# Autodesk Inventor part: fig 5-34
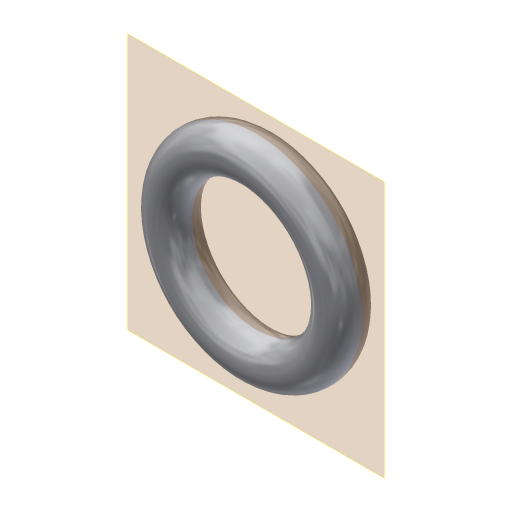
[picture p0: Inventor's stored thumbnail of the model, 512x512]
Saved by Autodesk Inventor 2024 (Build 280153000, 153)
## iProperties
Created: 2010-02
Part Number: fig 5-34
Document SubType Name: Modeling
Designer: CADSoft
Density: 1 g/cm^3
Material: Generic
Appearance: Default
Author: CADSoft
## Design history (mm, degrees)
sketch "Sketch1"
  geometry: L1 (0, 21.37)-(0, -16.247); C1 r 5 at (20.026, 0); 1 further point
  constraints: 2 end point, 1 centre point
  dimensions: "d0" = 10 diameter of C1
revolve "Revolution1" sketch "Sketch1" stored, may be unused: angle "d1" = 90 deg
workplane "Work Plane1"
body "Solid1"
